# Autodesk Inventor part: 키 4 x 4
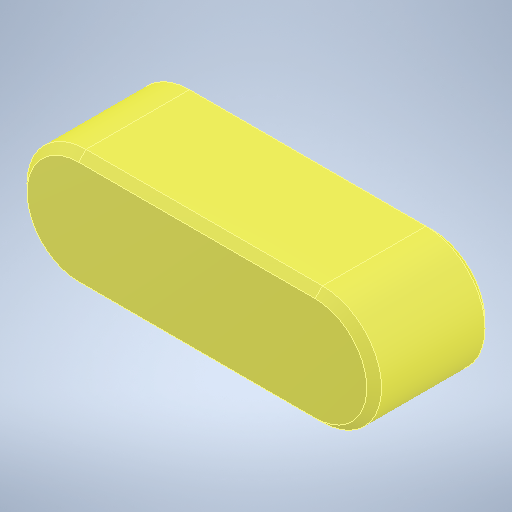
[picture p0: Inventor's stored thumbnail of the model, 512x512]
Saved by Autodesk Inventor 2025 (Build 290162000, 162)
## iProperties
Created: 2024-08
Part Number: 키 4 x 4
Material: 강철, 연강
Description: 키 및 해당 키홈
Document SubType Name: Modeling
Designer: onair
Density: 7.86 g/cm^3
Appearance: 기본값
Author: jhkim
Sending System: Autodesk Inventor 2025
Preprocessor: ST-DEVELOPER v20
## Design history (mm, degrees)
feature "Solid1"
node "솔리드1"
